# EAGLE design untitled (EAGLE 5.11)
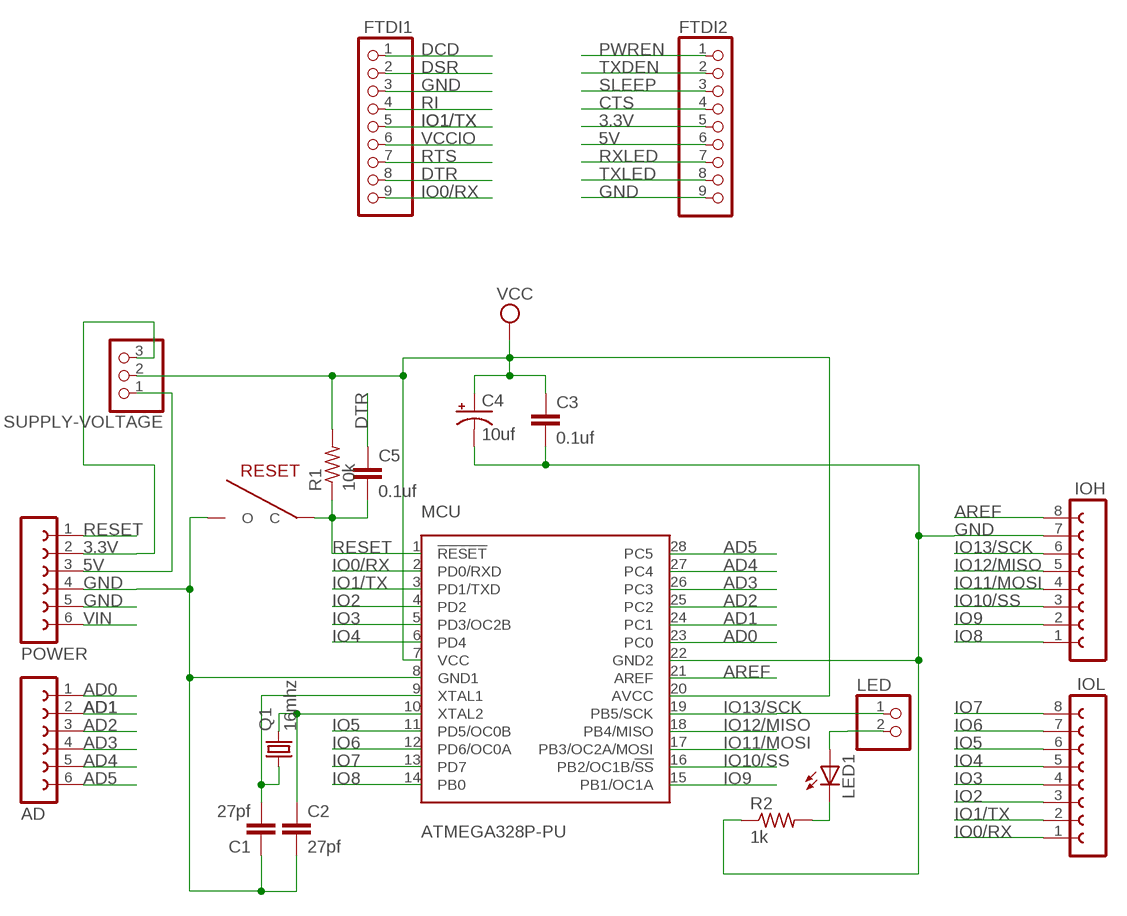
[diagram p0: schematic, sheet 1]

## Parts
AD  FE06-1  [FE06]
C1  27pf  C-EU050-055X075  [C050-055X075]
C2  27pf  C-EU050-055X075  [C050-055X075]
C3  0.1uf  C-EU050-055X075  [C050-055X075]
C4  10uf  CPOL-USE2-5  [E2-5]
C5  0.1uf  C-EU050-055X075  [C050-055X075]
FTDI1  PINHD-1X9  [1X09]
FTDI2  PINHD-1X9  [1X09]
IOH  FE08-1  [FE08]
IOL  FE08-1  [FE08]
LED  PINHD-1X2  [1X02]
LED1  LED3MM  [LED3MM]
MCU  ATMEGA328P-PU  [DIL28-3]
POWER  FE06-1  [FE06]
Q1  16mhz  CRYSTALHC49U-V  [HC49U-V]
R1  10k  R-US_0309/10  [0309/10]
R2  1k  R-US_0309/10  [0309/10]
RESET  SWITCH-SPST  [2SIL-0.1IN]
SUPPLY-VOLTAGE  PINHD-1X3  [1X03]

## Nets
3.3V: FTDI2.5 POWER.2 SUPPLY-VOLTAGE.3
5V: FTDI2.6 POWER.3 SUPPLY-VOLTAGE.1
AD0: AD.1 MCU.23(PC0)
AD1: AD.2 MCU.24(PC1)
AD2: AD.3 MCU.25(PC2)
AD3: AD.4 MCU.26(PC3)
AD4: AD.5 MCU.27(PC4)
AD5: AD.6 MCU.28(PC5)
AREF: IOH.8 MCU.21(AREF)
CTS: FTDI2.4
DCD: FTDI1.1
DSR: FTDI1.2
DTR: C5.1 FTDI1.8
GND: C1.1 C2.2 C3.2 C4.- FTDI1.3 FTDI2.9 IOH.7 MCU.8(GND1) MCU.22(GND2) POWER.4 POWER.5 R2.1 RESET.2(O)
IO0/RX: FTDI1.9 IOL.1 MCU.2(PD0/RXD)
IO1/TX: FTDI1.5 IOL.2 MCU.3(PD1/TXD)
IO2: IOL.3 MCU.4(PD2)
IO3: IOL.4 MCU.5(PD3/OC2B)
IO4: IOL.5 MCU.6(PD4)
IO5: IOL.6 MCU.11(PD5/OC0B)
IO6: IOL.7 MCU.12(PD6/OC0A)
IO7: IOL.8 MCU.13(PD7)
IO8: IOH.1 MCU.14(PB0)
IO9: IOH.2 MCU.15(PB1/OC1A)
IO10/SS: IOH.3 MCU.16(PB2/OC1B/!SS)
IO11/MOSI: IOH.4 MCU.17(PB3/OC2A/MOSI)
IO12/MISO: IOH.5 MCU.18(PB4/MISO)
IO13/SCK: IOH.6 LED.1 MCU.19(PB5/SCK)
N$1: C1.2 MCU.9(XTAL1) Q1.1
N$2: C2.1 MCU.10(XTAL2) Q1.2
N$3: LED1.A LED.2
N$4: LED1.K(C) R2.2
PWREN: FTDI2.1
RESET: C5.2 MCU.1(!RESET) POWER.1 R1.1 RESET.1(C)
RI: FTDI1.4
RTS: FTDI1.7
RXLED: FTDI2.7
SLEEP: FTDI2.3
TXDEN: FTDI2.2
TXLED: FTDI2.8
VCC: C3.1 C4.+ MCU.7(VCC) MCU.20(AVCC) R1.2 SUPPLY-VOLTAGE.2
VCCIO: FTDI1.6
VIN: POWER.6

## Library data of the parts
AD POWER = con-lsta:FE06-1: FEMALE HEADER; OC_FARNELL: unknown; OC_NEWARK: unknown
C1-C3 C5 = rcl:C-EU: CAPACITOR, European symbol
C4 = rcl:CPOL-US: POLARIZED CAPACITOR, American symbol
FTDI1 FTDI2 = pinhead:PINHD-1X9: PIN HEADER
IOH IOL = con-lsta:FE08-1: FEMALE HEADER; OC_FARNELL: unknown; OC_NEWARK: unknown
LED = pinhead:PINHD-1X2: PIN HEADER
LED1 = SparkFun:LED: LEDs
MCU = trl:ATMEGA328P-PU
Q1 = crystal:CRYSTAL: CRYSTAL; OC_FARNELL: 1666969; OC_NEWARK: unknown
R1 R2 = resistor:R-US_: RESISTOR, American symbol
RESET = trl:SWITCH-SPST
SUPPLY-VOLTAGE = pinhead:PINHD-1X3: PIN HEADER

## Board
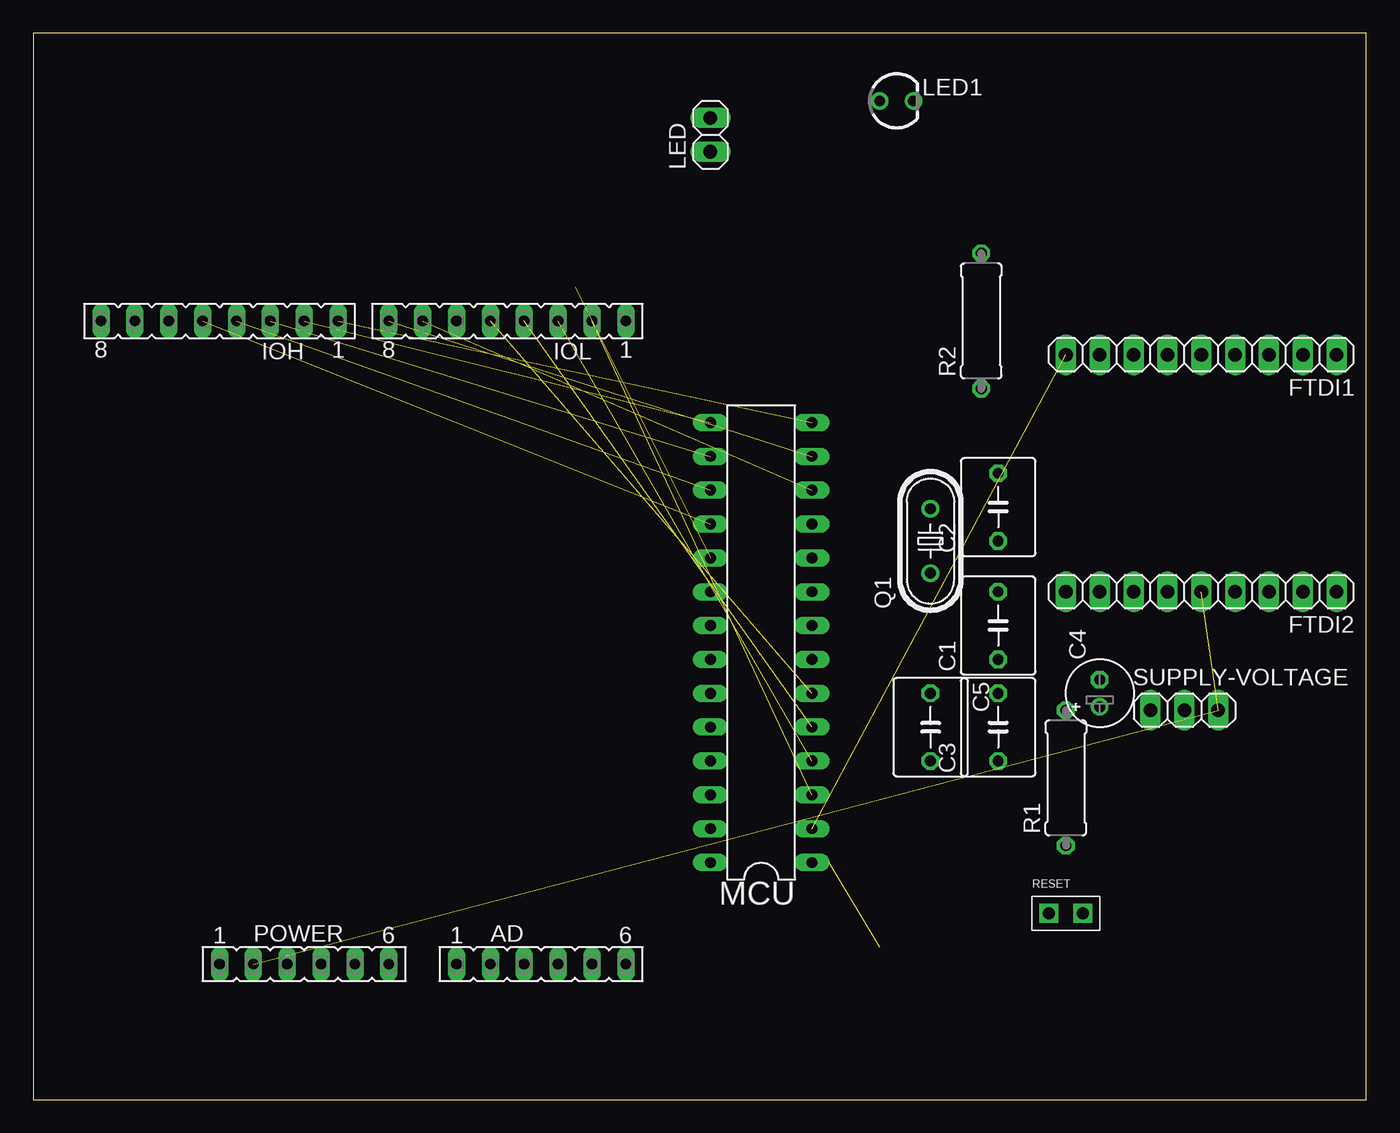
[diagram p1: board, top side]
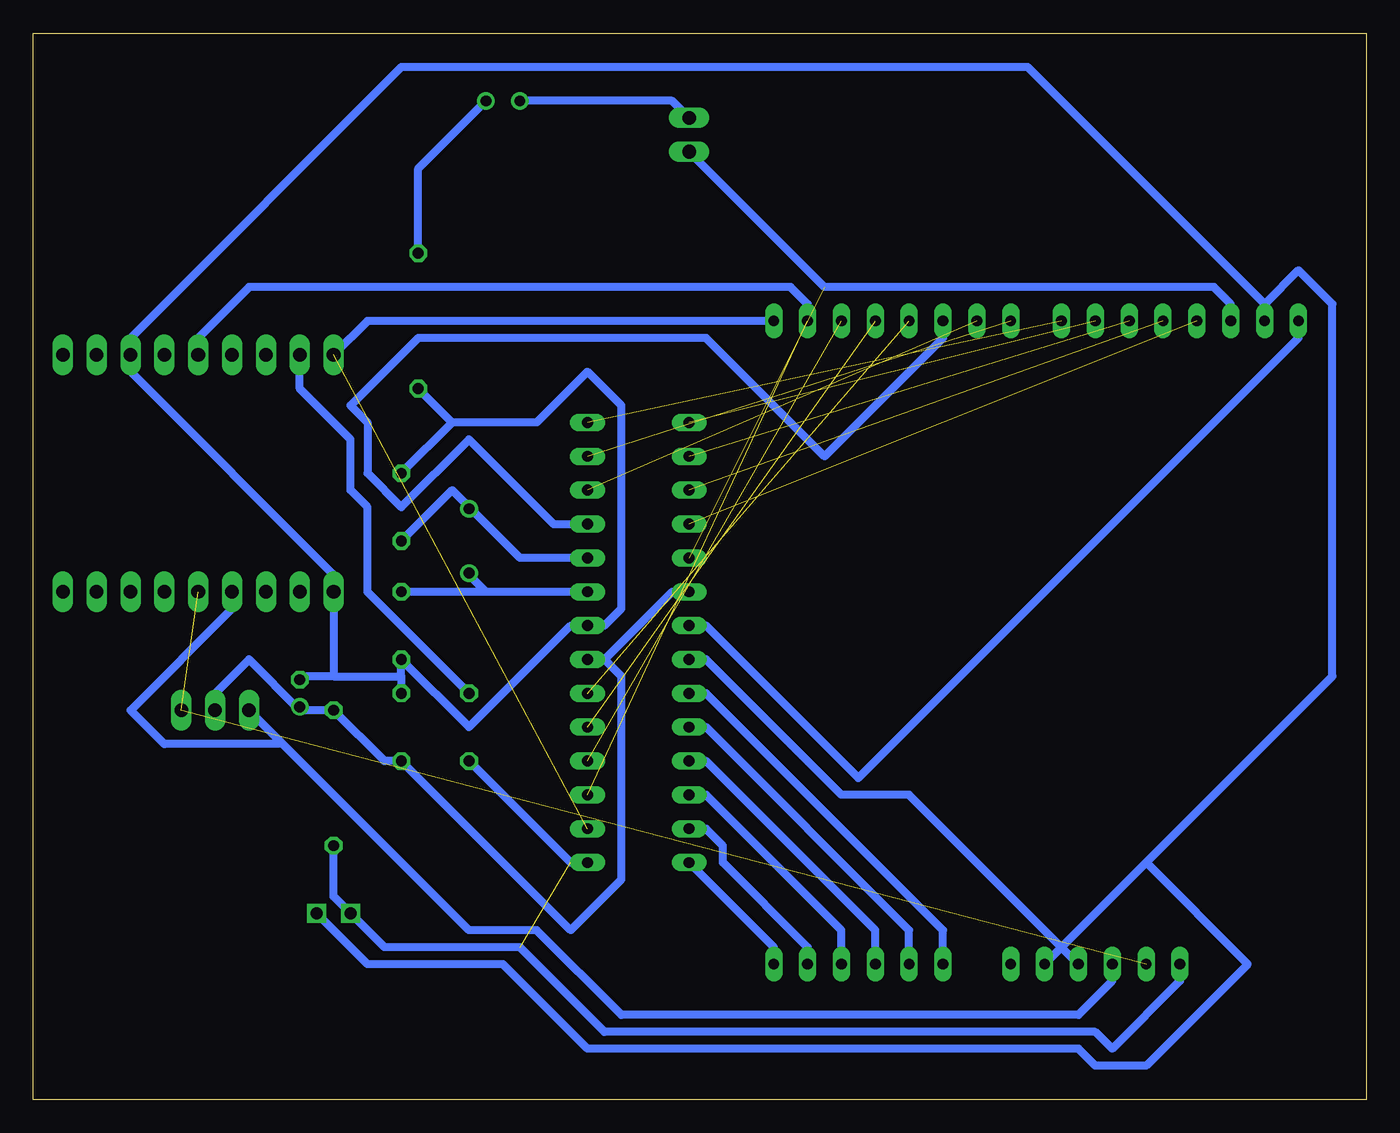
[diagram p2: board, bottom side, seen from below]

Size 100 x 80 mm. Coordinates in mm from the lower left corner, seen from the top.
Outline: 0,0 100,0 100,80 0,80 0,0
Copper layers (1*16): Top 0.035mm / dielectric 1.5mm / Bottom 0.035mm
Design rules "default *": minimum track width 24mil, minimum drill 24mil, track to track 16mil, track to pad 16mil, pad to pad 16mil, via to via 16mil, smd to smd 16mil, copper to edge 40mil, drill to drill 16mil, minimum pad ring 10mil, minimum via ring 8mil, stop-mask expansion 4mil, vias tented up to drill 0mil, thermal gap 10mil

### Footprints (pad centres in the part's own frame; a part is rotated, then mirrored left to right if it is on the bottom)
FE06 = drill 0.813 long: 1 -6.35,0; 2 -3.81,0; 3 -1.27,0; 4 1.27,0; 5 3.81,0; 6 6.35,0
C050-055X075 = drill 0.813 octagon: 1 -2.54,0; 2 2.54,0
E2-5 = drill 0.813 pad 1.27 round: + -1.016,0 | drill 0.813 pad 1.27 octagon: - 1.016,0
1X09 = drill 1.016 long: 1 -10.16,0; 2 -7.62,0; 3 -5.08,0; 4 -2.54,0; 5 0,0; 6 2.54,0; 7 5.08,0; 8 7.62,0; 9 10.16,0
FE08 = drill 0.813 long: 1 -8.89,0; 2 -6.35,0; 3 -3.81,0; 4 -1.27,0; 5 1.27,0; 6 3.81,0; 7 6.35,0; 8 8.89,0
1X02 = drill 1.016 long: 1 -1.27,0; 2 1.27,0
LED3MM = drill 0.813 round: A -1.27,0; K 1.27,0
DIL28-3 = drill 0.813 long: 1 -16.51,-3.81; 2 -13.97,-3.81; 3 -11.43,-3.81; 4 -8.89,-3.81; 5 -6.35,-3.81; 6 -3.81,-3.81; 7 -1.27,-3.81; 8 1.27,-3.81; 9 3.81,-3.81; 10 6.35,-3.81; 11 8.89,-3.81; 12 11.43,-3.81; 13 13.97,-3.81; 14 16.51,-3.81; 15 16.51,3.81; 16 13.97,3.81; 17 11.43,3.81; 18 8.89,3.81; 19 6.35,3.81; 20 3.81,3.81; 21 1.27,3.81; 22 -1.27,3.81; 23 -3.81,3.81; 24 -6.35,3.81; 25 -8.89,3.81; 26 -11.43,3.81; 27 -13.97,3.81; 28 -16.51,3.81
HC49U-V = drill 0.813 round: 1 -2.413,0; 2 2.413,0
0309/10 = drill 0.813 octagon: 1 -5.08,0; 2 5.08,0
2SIL-0.1IN = drill 0.9 pad 1.422 square: 1 -1.27,0; 2 1.27,0
1X03 = drill 1.016 long: 1 -2.54,0; 2 0,0; 3 2.54,0

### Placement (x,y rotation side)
AD  38.1,10.16 0 top
C1  72.39,35.56 90 top
C2  72.39,44.45 90 top
C3  72.39,27.94 90 top
C4  80.01,30.48 90 top
C5  67.31,27.94 270 top
FTDI1  87.63,55.88 180 top
FTDI2  87.63,38.1 180 top
IOH  13.97,58.42 180 top
IOL  35.56,58.42 180 top
LED  50.8,72.39 90 top
LED1  64.77,74.93 0 top
MCU  54.61,34.29 90 top
POWER  20.32,10.16 0 top
Q1  67.31,41.91 90 top
R1  77.47,24.13 90 top
R2  71.12,58.42 90 top
RESET  77.47,13.97 0 top
SUPPLY-VOLTAGE  86.36,29.21 0 top

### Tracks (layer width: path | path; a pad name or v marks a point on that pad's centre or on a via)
3.3V  (2 unrouted)
5V
  Bottom 0.61: POWER.3 19.05,8.89 21.59,6.35 55.88,6.35 62.23,12.7 67.31,12.7 81.28,26.67 | 81.28,26.67 SUPPLY-VOLTAGE.1 | FTDI2.6 85.09,36.83 92.71,29.21 90.17,26.67 81.28,26.67
AD0
  Bottom 0.61: AD.1 31.75,12.7 49.53,30.48 MCU.23
AD1
  Bottom 0.61: AD.2 34.29,12.7 49.53,27.94 MCU.24
AD2
  Bottom 0.61: AD.3 36.83,12.7 49.53,25.4 MCU.25
AD3
  Bottom 0.61: AD.4 39.37,12.7 49.53,22.86 MCU.26
AD4
  Bottom 0.61: AD.5 41.91,11.43 48.26,17.78 48.26,19.05 49.53,20.32 MCU.27
AD5
  Bottom 0.61: AD.6 44.45,11.43 MCU.28
AREF
  Bottom 0.61: IOH.8 5.08,57.15 38.1,24.13 49.53,35.56 MCU.21
DTR
  Bottom 0.61: C5.1 74.93,38.1 74.93,44.45 76.2,45.72 76.2,49.53 80.01,53.34 FTDI1.8
GND
  Bottom 0.61: 68.58,50.8 C2.2 | 68.58,50.8 R2.1 | 72.39,31.75 C1.1 67.31,27.94 59.69,35.56 MCU.8 57.15,35.56 55.88,36.83 55.88,52.07 58.42,54.61 62.23,50.8 68.58,50.8 | 72.39,31.75 C3.2 | 77.47,31.75 72.39,31.75 | 77.47,31.75 80.01,31.75 C4.- | 77.47,31.75 FTDI2.9 77.47,39.37 92.71,54.61 FTDI1.3 92.71,57.15 72.39,77.47 25.4,77.47 7.62,59.69 | 7.62,59.69 IOH.7 7.62,59.69 | 7.62,59.69 5.08,62.23 2.54,59.69 2.54,31.75 16.51,17.78 | 16.51,17.78 22.86,11.43 | 22.86,11.43 POWER.4 | 22.86,11.43 POWER.5 | MCU.22 49.53,33.02 39.37,22.86 34.29,22.86 22.86,11.43 | RESET.2 74.93,10.16 64.77,10.16 58.42,3.81 21.59,3.81 20.32,2.54 16.51,2.54 8.89,10.16 16.51,17.78
IO0/RX  (1 unrouted)
  Bottom 0.61: IOL.1 74.93,58.42 FTDI1.9
IO1/TX  (1 unrouted)
  Bottom 0.61: IOL.2 41.91,59.69 43.18,60.96 83.82,60.96 87.63,57.15 FTDI1.5
IO2  (1 unrouted)
IO3  (1 unrouted)
IO4  (1 unrouted)
IO5
  Bottom 0.61: IOL.6 31.75,57.15 40.64,48.26 49.53,57.15 71.12,57.15 76.2,52.07 74.93,50.8 74.93,46.99 72.39,44.45 67.31,49.53 60.96,43.18 MCU.11
IO6  (1 unrouted)
IO7  (1 unrouted)
IO8  (1 unrouted)
IO9  (1 unrouted)
IO10/SS  (1 unrouted)
IO11/MOSI  (1 unrouted)
IO12/MISO  (1 unrouted)
IO13/SCK  (1 unrouted)
  Bottom 0.61: IOH.6 10.16,59.69 11.43,60.96 40.64,60.96 LED.1
N$1
  Bottom 0.61: MCU.9 66.04,38.1 | 66.04,38.1 67.31,39.37 Q1.1 | 66.04,38.1 C1.2
N$2
  Bottom 0.61: MCU.10 63.5,40.64 67.31,44.45 | 67.31,44.45 Q1.2 67.31,44.45 | C2.1 68.58,45.72 67.31,44.45
N$3
  Bottom 0.61: LED1.A 52.07,74.93 LED.2
N$4
  Bottom 0.61: R2.2 71.12,69.85 LED1.K
RESET  (1 unrouted)
  Bottom 0.61: MCU.1 59.69,17.78 C5.2 | POWER.1 13.97,8.89 19.05,3.81 20.32,5.08 57.15,5.08 63.5,11.43 73.66,11.43 RESET.1 77.47,15.24 R1.1
VCC
  Bottom 0.61: 57.15,33.02 MCU.7 57.15,33.02 | 57.15,33.02 52.07,38.1 MCU.20 | 80.01,29.21 R1.2 73.66,25.4 C3.1 59.69,12.7 55.88,16.51 55.88,31.75 57.15,33.02 | 80.01,29.21 C4.+ 80.01,29.21 | SUPPLY-VOLTAGE.2 86.36,30.48 83.82,33.02 80.01,29.21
